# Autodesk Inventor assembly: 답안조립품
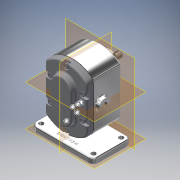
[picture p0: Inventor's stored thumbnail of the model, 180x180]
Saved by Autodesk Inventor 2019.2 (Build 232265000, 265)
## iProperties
Created: 2019-03
Part Number: 답안조립품
Material: 일반
Document SubType Name: Assembly
Designer: User
Author: User
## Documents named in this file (10)
- C:\Users\User\Desktop\490307V1008\답안조립품.iam
- C:\Users\User\Desktop\490307V1008\본체.ipt
- C:\Users\User\Desktop\490307V1008\커버.ipt
- C:\Users\User\Desktop\490307V1008\서브축.ipt
- C:\Users\User\Desktop\490307V1008\베어링부시.ipt
- C:\Users\User\Desktop\490307V1008\키 6 x 6 x 18.ipt
- C:\Users\User\Desktop\490307V1008\스퍼기어.ipt
- C:\Users\User\Desktop\490307V1008\메인축.ipt
- C:\Users\User\Desktop\490307V1008\개스킷.ipt
- C:\Users\User\Desktop\490307V1008\볼트 M5.ipt
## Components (1 placed, 1 different names)
1. 개스킷:1
